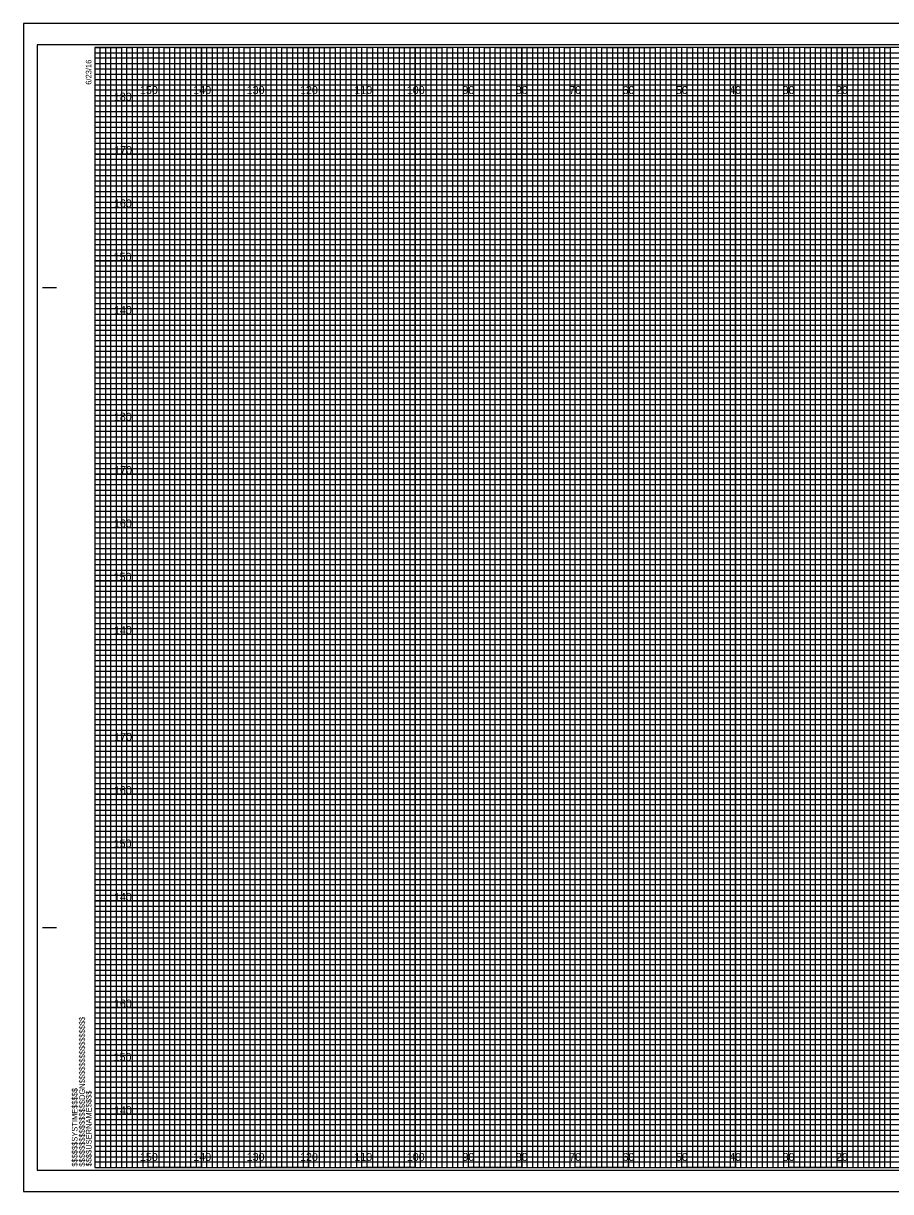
# Model space of a CAD drawing. Extents: x -13 to 323, y -5 to 4834.
# Drawn here: x -13.4 to 149.1, y 215.5 to 434.5 of the extents above; entities that cross this region are included whole.
import ezdxf

# ---------------------------------------------------------------- set-up
doc = ezdxf.new("R2010")
doc.units = 0
for name, color, linetype in [('Exist Cross Section Cell', 7, 'Continuous'), ('Exist XS Center Line Elevation Label', 7, 'Continuous'), ('Exist XS Ground Line', 7, 'Continuous'), ('Prop CMT Pvmt Course 1', 7, 'Continuous'), ('Prop CMT Pvmt Course 2', 7, 'Continuous'), ('Prop CMT Pvmt Course 3', 7, 'Continuous'), ('Prop CMT Pvmt Surface Shoulder', 7, 'Continuous'), ('Prop CMT Shld Paved Course 1', 7, 'Continuous'), ('Prop CMT Shld Paved Course 2', 7, 'Continuous'), ('Prop CMT Shld Paved Course 3', 7, 'Continuous'), ('Prop CMT Slope Grass', 7, 'Continuous')]:
    doc.layers.add(name, color=color, linetype=linetype)

msp = doc.modelspace()

# ---------------------------------------------------------------- linework, layer by layer
at = {"layer": 'Exist XS Center Line Elevation Label'}
for points in [[(0, 430), (5, 430), (5, 220), (15, 220), (15, 430), (25, 430), (25, 220), (35, 220), (35, 430), (45, 430), (45, 220), (55, 220), (55, 430), (65, 430), (65, 220), (75, 220), (75, 430), (85, 430), (85, 220), (95, 220), (95, 430), (105, 430), (105, 220), (115, 220), (115, 430), (125, 430), (125, 220), (135, 220), (135, 430), (145, 430), (145, 220), (155, 220)], [(0, 425), (275, 425)], [(0, 405), (320, 405), (320, 415), (0, 415)], [(0, 385), (320, 385), (320, 395), (0, 395)], [(0, 365), (320, 365), (320, 375), (0, 375)], [(0, 345), (320, 345), (320, 355), (0, 355)], [(0, 325), (320, 325), (320, 335), (0, 335)], [(0, 305), (320, 305), (320, 315), (0, 315)], [(0, 285), (320, 285), (320, 295), (0, 295)], [(0, 265), (320, 265), (320, 275), (0, 275)], [(0, 245), (320, 245), (320, 255), (0, 255)], [(0, 225), (320, 225), (320, 235), (0, 235)]]:
    msp.add_lwpolyline(points, dxfattribs=at)
at = {"layer": 'Exist XS Ground Line'}
for p, q in [((10, 430), (0, 430)), ((10, 220), (10, 430)), ((30, 430), (20, 430)), ((20, 430), (20, 220)), ((30, 220), (30, 430)), ((50, 430), (40, 430)), ((40, 430), (40, 220)), ((50, 220), (50, 430)), ((70, 430), (60, 430)), ((60, 430), (60, 220)), ((70, 220), (70, 430)), ((90, 430), (80, 430)), ((80, 430), (80, 220)), ((90, 220), (90, 430)), ((110, 430), (100, 430)), ((100, 430), (100, 220)), ((110, 220), (110, 430)), ((130, 430), (120, 430)), ((120, 430), (120, 220)), ((130, 220), (130, 430)), ((150, 430), (140, 430)), ((140, 430), (140, 220)), ((20, 220), (10, 220)), ((40, 220), (30, 220)), ((60, 220), (50, 220)), ((80, 220), (70, 220)), ((100, 220), (90, 220)), ((120, 220), (110, 220)), ((140, 220), (130, 220))]:
    msp.add_line(p, q, dxfattribs=at)
for points in [[(0, 420), (320, 420), (320, 410), (0, 410)], [(0, 400), (320, 400), (320, 390), (0, 390)], [(0, 380), (320, 380), (320, 370), (0, 370)], [(0, 360), (320, 360), (320, 350), (0, 350)], [(0, 340), (320, 340), (320, 330), (0, 330)], [(0, 320), (320, 320), (320, 310), (0, 310)], [(0, 300), (320, 300), (320, 290), (0, 290)], [(0, 280), (320, 280), (320, 270), (0, 270)], [(0, 260), (320, 260), (320, 250), (0, 250)], [(0, 240), (320, 240), (320, 230), (0, 230)]]:
    msp.add_lwpolyline(points, dxfattribs=at)
at = {"layer": 'Prop CMT Pvmt Course 1'}
for points in [[(0, 220), (1, 220), (1, 430), (2, 430), (2, 220)], [(2, 220), (3, 220), (3, 430), (4, 430), (4, 220)], [(5, 220), (6, 220), (6, 430), (7, 430), (7, 220)], [(7, 220), (8, 220), (8, 430), (9, 430), (9, 220)], [(10, 220), (11, 220), (11, 430), (12, 430), (12, 220)], [(12, 220), (13, 220), (13, 430), (14, 430), (14, 220)], [(15, 220), (16, 220), (16, 430), (17, 430), (17, 220)], [(17, 220), (18, 220), (18, 430), (19, 430), (19, 220)], [(20, 220), (21, 220), (21, 430), (22, 430), (22, 220)], [(22, 220), (23, 220), (23, 430), (24, 430), (24, 220)], [(25, 220), (26, 220), (26, 430), (27, 430), (27, 220)], [(27, 220), (28, 220), (28, 430), (29, 430), (29, 220)], [(30, 220), (31, 220), (31, 430), (32, 430), (32, 220)], [(32, 220), (33, 220), (33, 430), (34, 430), (34, 220)], [(35, 220), (36, 220), (36, 430), (37, 430), (37, 220)], [(37, 220), (38, 220), (38, 430), (39, 430), (39, 220)], [(40, 220), (41, 220), (41, 430), (42, 430), (42, 220)], [(42, 220), (43, 220), (43, 430), (44, 430), (44, 220)], [(45, 220), (46, 220), (46, 430), (47, 430), (47, 220)], [(47, 220), (48, 220), (48, 430), (49, 430), (49, 220)], [(50, 220), (51, 220), (51, 430), (52, 430), (52, 220)], [(52, 220), (53, 220), (53, 430), (54, 430), (54, 220)], [(55, 220), (56, 220), (56, 430), (57, 430), (57, 220)], [(57, 220), (58, 220), (58, 430), (59, 430), (59, 220)], [(60, 220), (61, 220), (61, 430), (62, 430), (62, 220)], [(62, 220), (63, 220), (63, 430), (64, 430), (64, 220)], [(65, 220), (66, 220), (66, 430), (67, 430), (67, 220)], [(67, 220), (68, 220), (68, 430), (69, 430), (69, 220)], [(70, 220), (71, 220), (71, 430), (72, 430), (72, 220)], [(72, 220), (73, 220), (73, 430), (74, 430), (74, 220)], [(75, 220), (76, 220), (76, 430), (77, 430), (77, 220)], [(77, 220), (78, 220), (78, 430), (79, 430), (79, 220)], [(80, 220), (81, 220), (81, 430), (82, 430), (82, 220)], [(82, 220), (83, 220), (83, 430), (84, 430), (84, 220)], [(85, 220), (86, 220), (86, 430), (87, 430), (87, 220)], [(87, 220), (88, 220), (88, 430), (89, 430), (89, 220)], [(90, 220), (91, 220), (91, 430), (92, 430), (92, 220)], [(92, 220), (93, 220), (93, 430), (94, 430), (94, 220)], [(95, 220), (96, 220), (96, 430), (97, 430), (97, 220)], [(97, 220), (98, 220), (98, 430), (99, 430), (99, 220)], [(100, 220), (101, 220), (101, 430), (102, 430), (102, 220)], [(102, 220), (103, 220), (103, 430), (104, 430), (104, 220)], [(105, 220), (106, 220), (106, 430), (107, 430), (107, 220)], [(107, 220), (108, 220), (108, 430), (109, 430), (109, 220)], [(110, 220), (111, 220), (111, 430), (112, 430), (112, 220)], [(112, 220), (113, 220), (113, 430), (114, 430), (114, 220)], [(115, 220), (116, 220), (116, 430), (117, 430), (117, 220)], [(117, 220), (118, 220), (118, 430), (119, 430), (119, 220)], [(120, 220), (121, 220), (121, 430), (122, 430), (122, 220)], [(122, 220), (123, 220), (123, 430), (124, 430), (124, 220)], [(125, 220), (126, 220), (126, 430), (127, 430), (127, 220)], [(127, 220), (128, 220), (128, 430), (129, 430), (129, 220)], [(130, 220), (131, 220), (131, 430), (132, 430), (132, 220)], [(132, 220), (133, 220), (133, 430), (134, 430), (134, 220)], [(135, 220), (136, 220), (136, 430), (137, 430), (137, 220)], [(137, 220), (138, 220), (138, 430), (139, 430), (139, 220)], [(140, 220), (141, 220), (141, 430), (142, 430), (142, 220)], [(142, 220), (143, 220), (143, 430), (144, 430), (144, 220)], [(145, 220), (146, 220), (146, 430), (147, 430), (147, 220)], [(147, 220), (148, 220), (148, 430), (149, 430), (149, 220)]]:
    msp.add_lwpolyline(points, dxfattribs=at)
at = {"layer": 'Prop CMT Pvmt Course 2'}
for p, q in [((323.3, 434.5), (-13.4, 434.5)), ((-13.4, 434.5), (-13.4, 215.5)), ((-13.4, 215.5), (323.3, 215.5))]:
    msp.add_line(p, q, dxfattribs=at)
at = {"layer": 'Prop CMT Pvmt Surface Shoulder'}
for p, q in [((-9.8, 385), (-7.3, 385)), ((-9.7, 385), (-7.2, 385)), ((-9.8, 265), (-7.3, 265)), ((-9.7, 265), (-7.2, 265)), ((0, 220), (0, 220)), ((0, 220), (0, 220)), ((0, 220), (0, 220)), ((0, 220), (0, 220)), ((0, 220), (0, 220)), ((0, 220), (0, 220)), ((0, 220), (0, 220))]:
    msp.add_line(p, q, dxfattribs=at)
msp.add_lwpolyline([(320, 430), (0, 430), (0, 220), (320, 220)], close=True, dxfattribs=at)
at = {"layer": 'Prop CMT Shld Paved Course 1'}
msp.add_lwpolyline([(-13.4, 215.5), (323.3, 215.5), (323.3, 434.5), (-13.4, 434.5)], close=True, dxfattribs=at)
at = {"layer": 'Prop CMT Shld Paved Course 2'}
msp.add_lwpolyline([(-10.8, 219.5), (322.4, 219.5), (322.4, 430.5), (-10.8, 430.5)], close=True, dxfattribs=at)
at = {"layer": 'Prop CMT Shld Paved Course 3'}
for p, q in [((10, 220), (10, 430)), ((20, 220), (20, 430)), ((30, 220), (30, 430)), ((40, 220), (40, 430)), ((50, 220), (50, 430)), ((60, 220), (60, 430)), ((70, 220), (70, 430)), ((80, 220), (80, 430)), ((90, 220), (90, 430)), ((100, 220), (100, 430)), ((110, 220), (110, 430)), ((120, 220), (120, 430)), ((130, 220), (130, 430)), ((140, 220), (140, 430)), ((0, 420), (320, 420)), ((0, 410), (320, 410)), ((0, 400), (320, 400)), ((0, 390), (320, 390)), ((0, 380), (320, 380)), ((0, 370), (320, 370)), ((0, 360), (320, 360)), ((0, 350), (320, 350)), ((0, 340), (320, 340)), ((0, 330), (320, 330)), ((0, 320), (320, 320)), ((0, 310), (320, 310)), ((0, 300), (320, 300)), ((0, 290), (320, 290)), ((0, 280), (320, 280)), ((0, 270), (320, 270)), ((0, 260), (320, 260)), ((0, 250), (320, 250)), ((0, 240), (320, 240)), ((0, 230), (320, 230))]:
    msp.add_line(p, q, dxfattribs=at)
at = {"layer": 'Prop CMT Slope Grass'}
for p, q in [((0, 429), (260, 429)), ((260, 427.98), (0, 427.98)), ((0, 427.98), (0, 427)), ((0, 427), (260, 427)), ((260, 425.89), (0, 425.89)), ((0, 425.89), (0, 424)), ((0, 424), (320, 424))]:
    msp.add_line(p, q, dxfattribs=at)
for points in [[(0, 423), (270, 423), (320, 423), (320, 422), (0, 422)], [(0, 421), (320, 421), (320, 419), (0, 419)], [(0, 418), (320, 418), (320, 417), (0, 416.98)], [(0, 416), (320, 416), (320, 414), (0, 414)], [(0, 413), (320, 413), (320, 412), (0, 412)], [(0, 411), (320, 411), (320, 409), (0, 409)], [(0, 408), (320, 408), (320, 407), (0, 407)], [(0, 406), (320, 406), (320, 404), (0, 404)], [(0, 403), (320, 403), (320, 402), (0, 402)], [(0, 401), (320, 401), (320, 399), (0, 399)], [(0, 398), (320, 398), (320, 397), (0, 397)], [(0, 396), (320, 396), (320, 393.95), (320, 393), (320, 392), (0, 392)], [(0, 394), (320, 394), (320, 393), (0, 393)], [(0, 391), (320, 391), (320, 389), (0, 389.03)], [(0, 389.03), (320, 389), (320, 388), (0, 388)], [(0, 387), (320, 387), (320, 386), (0, 386)], [(0, 384), (320, 384), (320, 383), (0, 383)], [(0, 382), (320, 382), (320, 381), (0, 381)], [(-0.07, 378.89), (320, 378.89), (320, 377.88), (-0.07, 377.88)], [(0, 377), (320, 377), (320, 376), (0, 376)], [(0, 374), (320, 374), (320, 373), (0, 373)], [(0, 372), (320, 372), (320, 371), (0, 371)], [(0, 369), (320, 369), (320, 368), (0, 368)], [(0, 367), (320, 367), (320, 366), (0, 366)], [(0, 364), (320, 364), (320, 363), (0, 363)], [(0, 362), (320, 362), (320, 361), (0, 361)], [(0, 359), (320, 359), (319.99, 357.98), (0, 358)], [(0, 357), (320, 357), (320, 356), (0, 356)], [(0, 354), (320, 354), (320, 353), (0, 353)], [(0, 352), (320, 352), (320, 351), (0, 351)], [(0, 349), (320, 349), (320, 348), (0, 348)], [(0, 347), (320, 347), (320, 346), (0, 346)], [(0, 344), (320, 344), (320, 343), (0, 343)], [(0, 342), (320, 342), (320, 341), (0, 341)], [(0, 339), (320, 339), (320, 338), (0, 338)], [(0, 336.99), (320.07, 336.91), (320, 336), (0, 336)], [(0, 334), (320, 334), (320, 333), (0, 333)], [(0, 332), (320, 332), (320, 331), (0, 331)], [(0, 329), (320, 329), (320, 328), (0, 328)], [(0, 327), (320, 327), (320, 326), (0, 326)], [(0, 324), (320, 324), (320, 323), (0, 323)], [(0, 322), (320, 322), (320, 321), (0, 321)], [(0, 319), (320, 319), (320, 318), (0, 318)], [(0, 317), (320, 317), (320, 316), (0, 316)], [(0, 314), (320, 314), (320, 313), (0, 313)], [(0, 312), (320, 312), (320, 311), (0, 311)], [(0, 309), (320, 309), (320, 308), (0, 308)], [(0, 307), (320, 307), (320, 306), (0, 306)], [(0, 304), (320, 304), (320, 303), (0, 303)], [(0, 302), (320, 302), (320, 301), (0, 301)], [(0, 299), (320, 299), (319.99, 297.98), (0, 298)], [(0, 297), (320, 297), (320, 296), (0, 296)], [(0, 294), (320, 294), (320, 293), (0, 293)], [(0, 292), (320, 292), (320, 291), (0, 291)], [(0, 289), (320, 289), (320, 288), (0, 288)], [(0, 287), (320, 287), (320, 286), (0, 286)], [(0, 284), (320, 284), (320, 283), (0, 283)], [(0, 282), (320, 282), (320, 281), (0, 281)], [(0, 279), (320, 279), (320, 278), (0, 278)], [(0, 276.99), (320.07, 276.91), (320, 276), (0, 276)], [(0, 274), (320, 274), (320, 273), (0, 273)], [(0, 272), (320, 272), (320, 271), (0, 271)], [(0, 269), (320, 269), (320, 268), (0, 268)], [(0, 267), (320, 267), (320, 266), (0, 266)], [(0, 264), (320, 264), (320, 263), (0, 263)], [(0, 262), (320, 262), (320, 261), (0, 261)], [(0, 259), (320, 259), (320, 258), (0, 258)], [(0, 257), (320, 257), (320, 256), (0, 256)], [(0, 254), (320, 254), (320, 253), (0, 253)], [(0, 252), (320, 252), (320, 251), (0, 251)], [(0, 249), (320, 249), (320, 248), (0, 248)], [(0, 247), (320, 247), (320, 246), (0, 246)], [(0, 244), (320, 244), (320, 243), (0, 243)], [(0, 242), (320, 242), (320, 241), (0, 241)], [(0, 239), (320, 239), (320, 238), (0, 238)], [(0, 237), (320, 237), (320, 236), (0, 236)], [(0, 234), (320, 234), (320, 233), (0, 233)], [(0, 232), (320, 232), (320, 231), (0, 231)], [(0, 229), (320, 229), (320, 228), (0, 228)], [(0, 227), (320, 227), (320, 226), (0, 226)], [(0, 224), (320, 224), (320, 223), (0, 223)], [(0, 222), (320, 222), (320, 221), (0, 221)]]:
    msp.add_lwpolyline(points, dxfattribs=at)

# ---------------------------------------------------------------- texts
at = {"layer": 'Exist Cross Section Cell'}
for s, p in [('150', (8.44, 421.25)), ('140', (18.44, 421.25)), ('130', (28.44, 421.25)), ('120', (38.44, 421.25)), ('110', (48.62, 421.25)), ('100', (58.44, 421.25)), ('90', (68.86, 421.25)), ('80', (78.86, 421.25)), ('70', (88.86, 421.25)), ('60', (98.86, 421.25)), ('50', (108.86, 421.25)), ('40', (118.86, 421.25)), ('30', (128.86, 421.25)), ('20', (138.86, 421.25)), ('150', (8.44, 221.25)), ('140', (18.44, 221.25)), ('130', (28.44, 221.25)), ('120', (38.44, 221.25)), ('110', (48.62, 221.25)), ('100', (58.44, 221.25)), ('90', (68.86, 221.25)), ('80', (78.86, 221.25)), ('70', (88.86, 221.25)), ('60', (98.86, 221.25)), ('50', (108.86, 221.25)), ('40', (118.86, 221.25)), ('30', (128.86, 221.25)), ('20', (138.86, 221.25))]:
    msp.add_text(s, height=1.5, dxfattribs=at).set_placement(p)
at = {"layer": 'Prop CMT Pvmt Course 3'}
for s, p in [('180', (3.55, 420)), ('170', (3.61, 410)), ('160', (3.57, 400)), ('150', (3.52, 390)), ('140', (3.57, 380)), ('180', (3.55, 360)), ('170', (3.61, 350)), ('160', (3.57, 340)), ('150', (3.52, 330)), ('140', (3.57, 320)), ('170', (3.61, 300)), ('160', (3.57, 290)), ('150', (3.52, 280)), ('140', (3.57, 270)), ('160', (3.57, 250)), ('150', (3.52, 240)), ('140', (3.57, 230))]:
    msp.add_text(s, height=1.5, dxfattribs=at).set_placement(p)
at = {"layer": 'Prop CMT Pvmt Surface Shoulder'}
for s, p in [('6/23/16', (-0.65, 423)), ('$$$$$$$$$$$$$$$$DGN$$$$$$$$$$$$$$$$', (-1.88, 220.18)), ('$$$$$$SYSTIME$$$$$', (-3.26, 220.18)), ('$$$$USERNAME$$$$', (-0.62, 220.23))]:
    msp.add_text(s, height=1.05, rotation=90, dxfattribs=at).set_placement(p)

doc.saveas('drawing.dxf')
